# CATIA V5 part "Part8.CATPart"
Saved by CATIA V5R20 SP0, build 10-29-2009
Part number: 9CS061215
Revision: ANY
Definition: UNKNOWN
Nomenclature: 9CS061215
Source: Unknown
Bounding box of the stored display mesh (mm): x -5.85 to 5.85, y 0 to 15, z -6 to 6
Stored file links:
  C:\Users\Utente\Desktop\IO LAVORO\3D X SITO CF\CUMSA\3D files PW\pw060630\pw060630_injection\Part8.CATPart
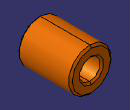
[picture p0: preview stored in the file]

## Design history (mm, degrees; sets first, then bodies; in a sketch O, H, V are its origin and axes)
Body1 "Revolución1" (main body)
  Solid1: solid without history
